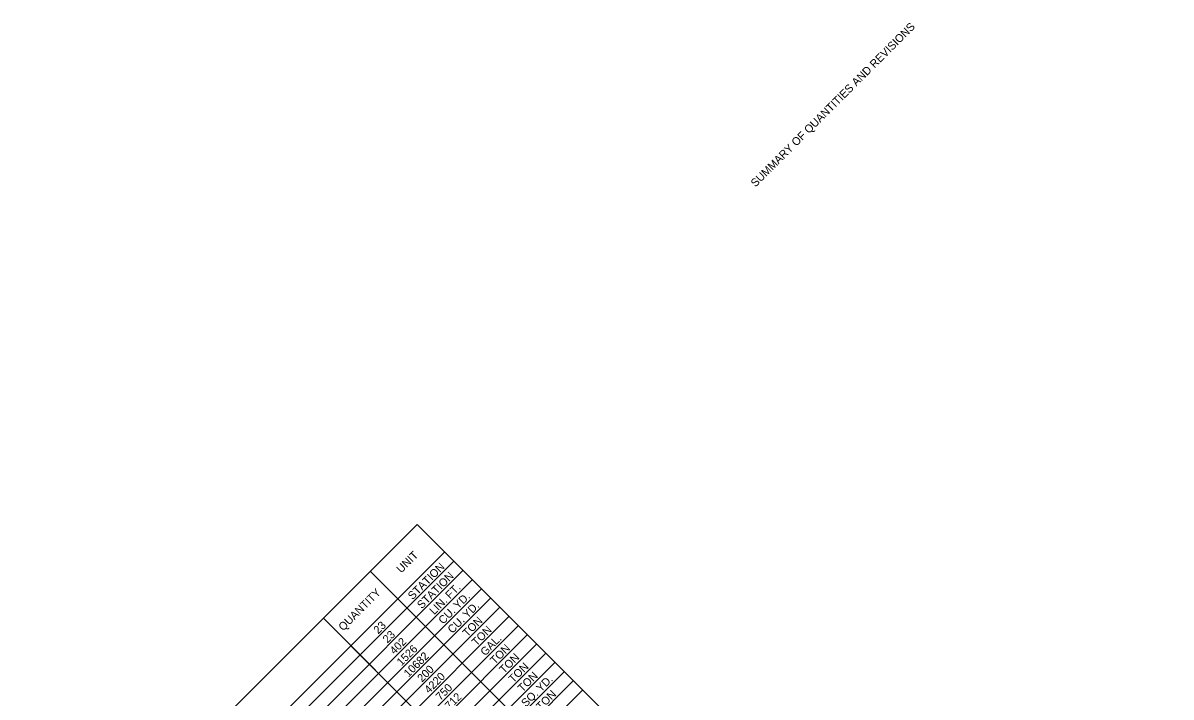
# Model space of a CAD drawing. Extents: x 1675667 to 1681231, y 227227 to 232694.
# Drawn here: x 1679879 to 1680739, y 232189 to 232694 of the extents above; entities that cross this region are included whole.
import ezdxf

# ---------------------------------------------------------------- set-up
doc = ezdxf.new("R2010")
doc.units = 0
doc.layers.add('Default', color=7, linetype='Continuous')
doc.layers.add('R_Border', color=7, linetype='Continuous')

msp = doc.modelspace()

# ---------------------------------------------------------------- linework, layer by layer
at = {"layer": 'Default'}
for p, q in [((1679701.21, 231844.97), (1680174.44, 232318.32)), ((1680739.5, 231753.4), (1680174.44, 232318.32)), ((1679721.89, 231824.29), (1680195.13, 232297.64)), ((1679728.79, 231817.4), (1680202.02, 232290.75)), ((1679735.68, 231810.5), (1680208.92, 232283.85)), ((1680704.34, 231718.24), (1680139.29, 232283.16)), ((1680580.23, 231842.32), (1680139.29, 232283.16)), ((1679742.58, 231803.61), (1680215.81, 232276.96)), ((1679749.47, 231796.72), (1680222.71, 232270.07)), ((1679756.37, 231789.82), (1680229.6, 232263.17)), ((1679763.26, 231782.93), (1680236.5, 232256.28)), ((1679770.16, 231776.04), (1680243.39, 232249.39)), ((1680669.19, 231683.07), (1680104.13, 232247.99)), ((1679777.05, 231769.14), (1680250.29, 232242.49)), ((1679783.95, 231762.25), (1680257.18, 232235.6)), ((1679790.84, 231755.36), (1680264.08, 232228.71)), ((1680545.07, 231807.16), (1680124.81, 232227.31)), ((1679797.74, 231748.46), (1680270.97, 232221.81)), ((1679804.63, 231741.57), (1680277.87, 232214.92)), ((1679811.53, 231734.68), (1680284.76, 232208.03)), ((1679818.42, 231727.78), (1680291.66, 232201.13)), ((1679825.32, 231720.89), (1680298.56, 232194.24))]:
    msp.add_line(p, q, dxfattribs=at)

# ---------------------------------------------------------------- texts
for s, p in [('UNIT', (1680162.48, 232281.42)), ('STATION', (1680170.99, 232261.41)), ('STATION', (1680177.89, 232254.52)), ('QUANTITY', (1680119.02, 232237.96)), (' FT.', (1680197.55, 232260.39)), ('LIN.', (1680187.2, 232250.04)), (' YD.', (1680203.62, 232252.67)), ('CU.', (1680193.93, 232242.98)), (' YD.', (1680210.52, 232245.78)), ('23', (1680145.28, 232235.69)), ('CU.', (1680200.83, 232236.09)), ('TON', (1680212.06, 232233.53)), ('23', (1680152.17, 232228.79)), ('TON', (1680218.95, 232226.64)), ('402', (1680157.44, 232220.28)), ('1526', (1680162.67, 232211.71)), ('GAL.', (1680225.37, 232219.26)), ('TON', (1680232.74, 232212.85)), ('10682', (1680167.94, 232203.19)), ('TON', (1680239.64, 232205.96)), ('200', (1680178.12, 232199.58)), ('TON', (1680246.53, 232199.06)), ('4220', (1680183.36, 232191.04)), ('TON', (1680253.43, 232192.17)), (' YD.', (1680265.68, 232190.63)), ('750', (1680191.91, 232185.79)), ('712', (1680198.82, 232178.91)), ('SQ.', (1680255.99, 232180.94)), ('TON', (1680267.22, 232178.38))]:
    msp.add_text(s, height=6, rotation=45.00703, dxfattribs=at).set_placement(p)
at = {"layer": 'R_Border'}
msp.add_text('SUMMARY OF QUANTITIES AND REVISIONS', height=6, rotation=45.00703, dxfattribs=at).set_placement((1680428.03, 232570.98))

doc.saveas('drawing.dxf')
